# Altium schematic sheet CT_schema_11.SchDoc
size 386 x 385 mm
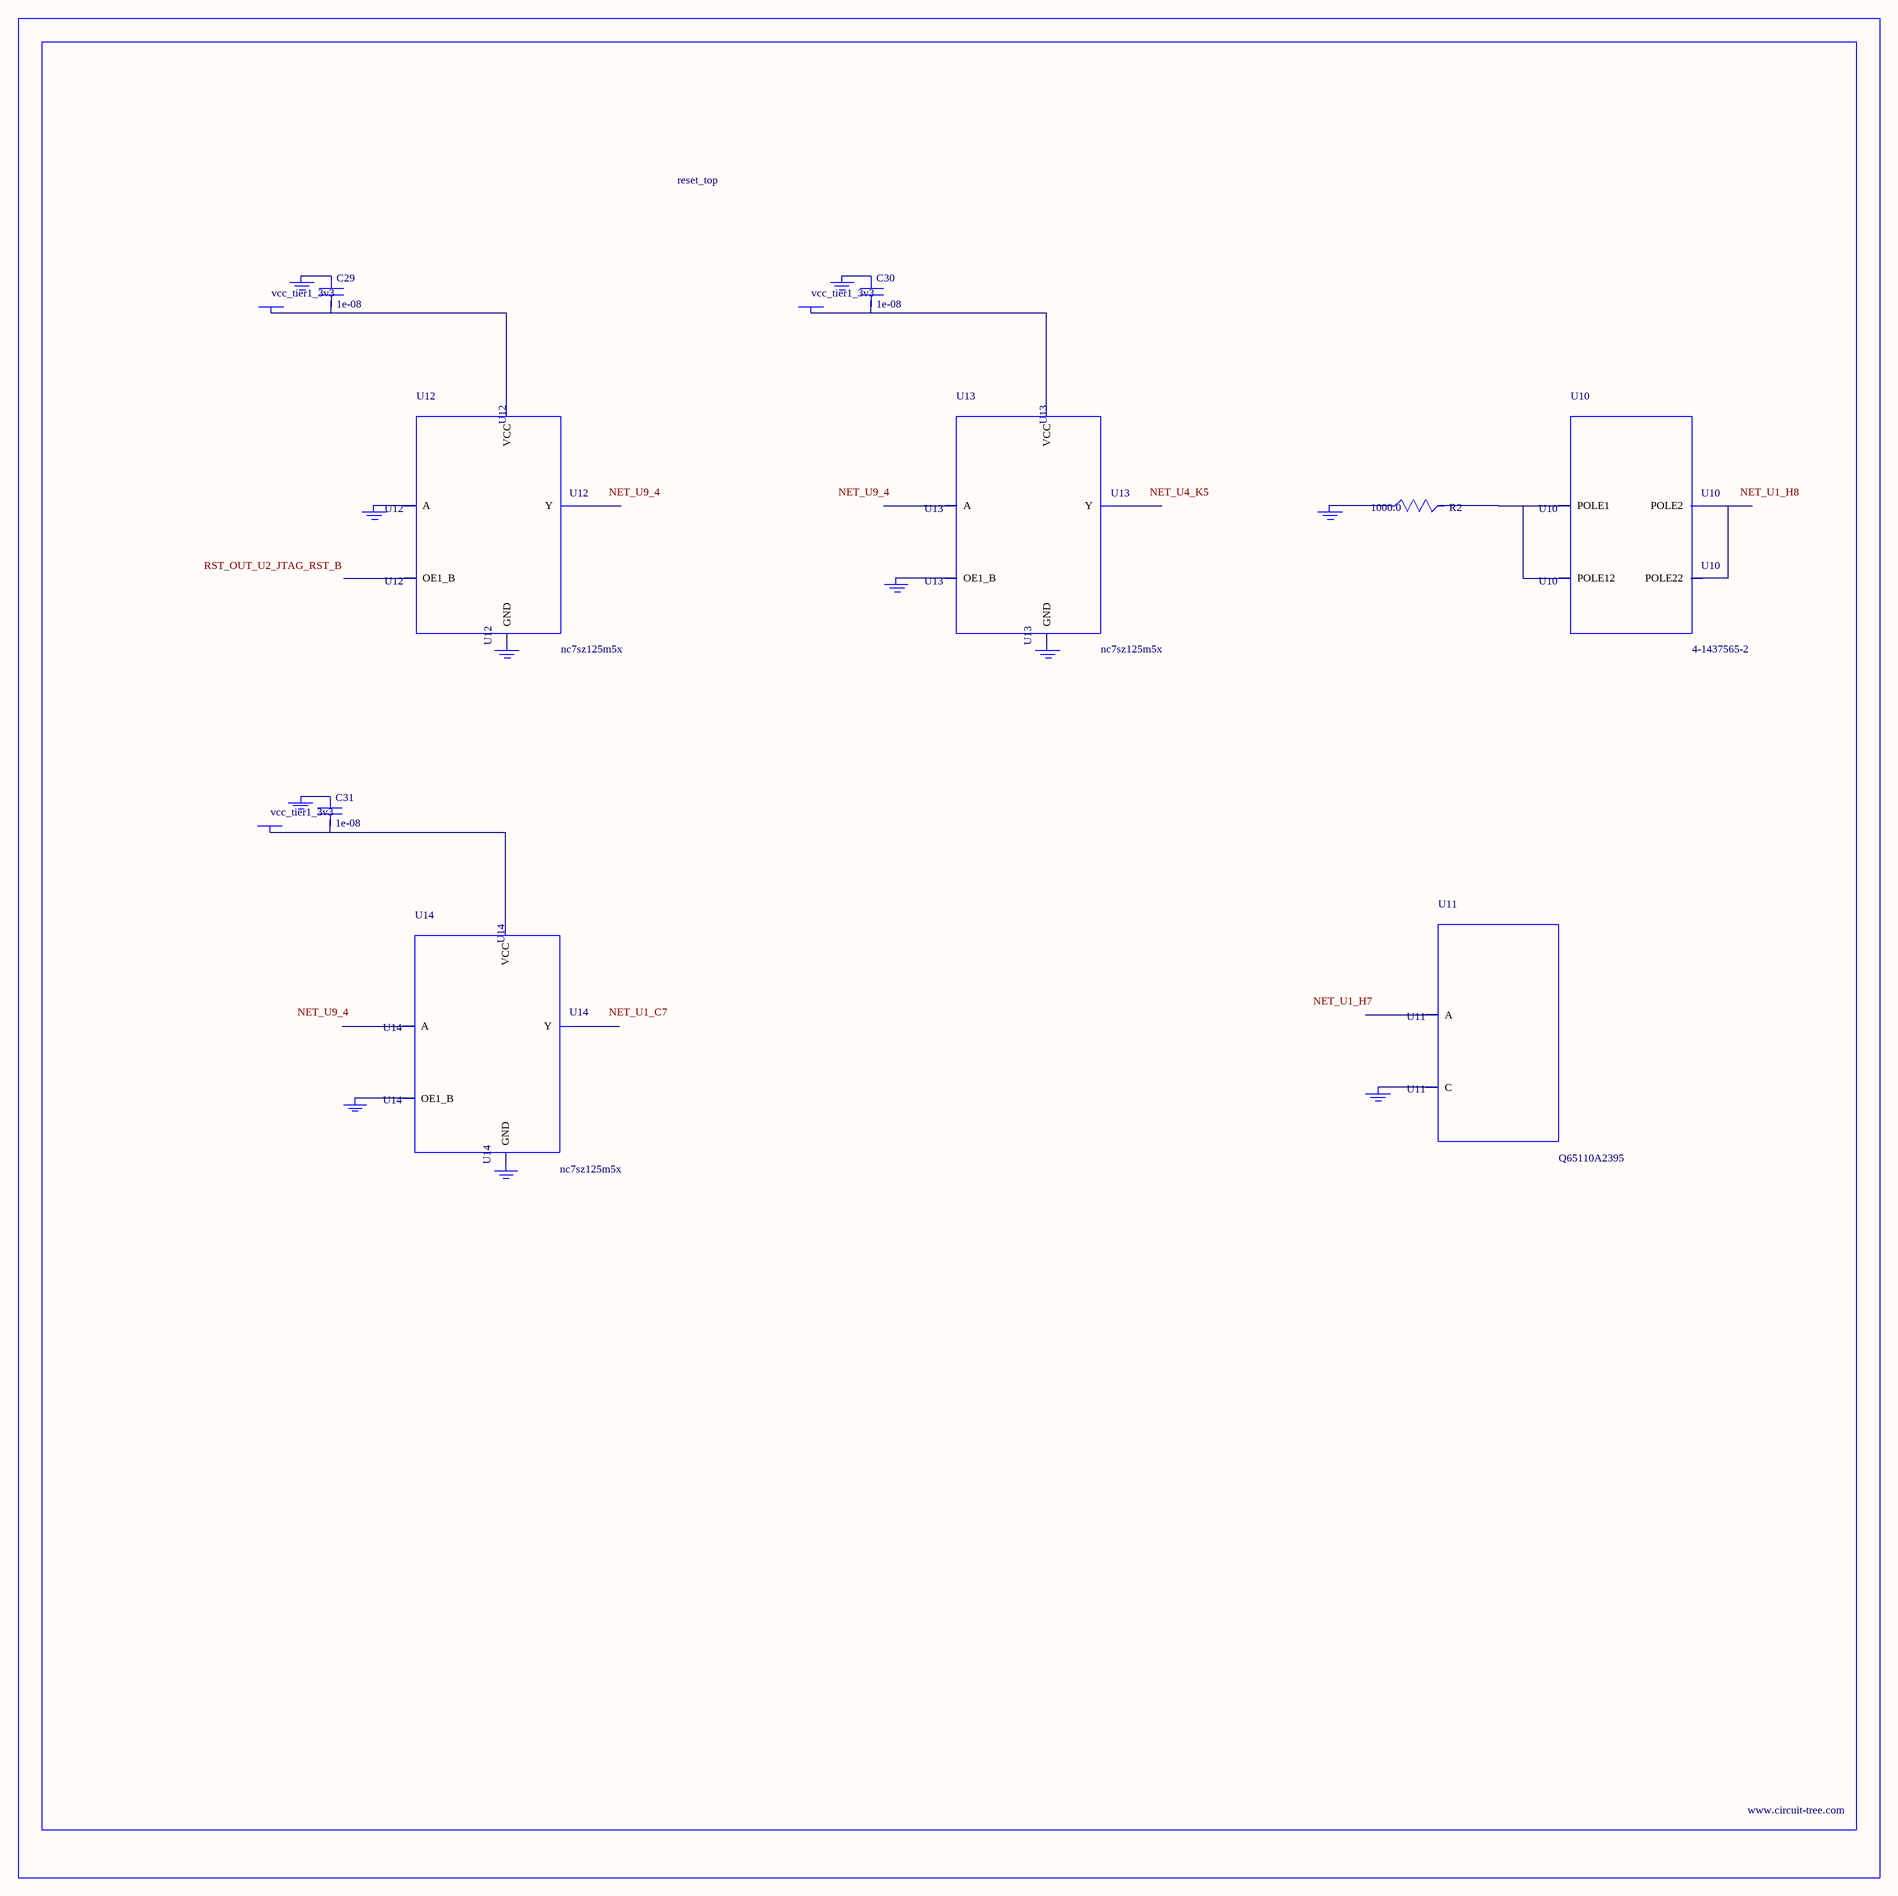
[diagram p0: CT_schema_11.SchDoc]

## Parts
BORDER10  (no value)
C29  1e-08  [C0402]
C30  1e-08  [C0402]
C31  1e-08  [C0402]
GND_INSTANCE_10_0  (no value)
GND_INSTANCE_10_1  (no value)
GND_INSTANCE_10_2  (no value)
GND_INSTANCE_10_3  (no value)
GND_INSTANCE_10_4  (no value)
GND_INSTANCE_10_5  (no value)
GND_INSTANCE_10_6  (no value)
GND_INSTANCE_10_7  (no value)
GND_INSTANCE_10_8  (no value)
GND_INSTANCE_10_9  (no value)
GND_INSTANCE_10_10  (no value)
POWER_INSTANCE_10_0  vcc_tier1_3v3
POWER_INSTANCE_10_1  vcc_tier1_3v3
POWER_INSTANCE_10_2  vcc_tier1_3v3
R2  1000.0  [R0603]
U10  4-1437565-2  [SW_4-1437565-2]
U11  Q65110A2395  [LGM67K-G1J2-24-Z]
U12  nc7sz125m5x  [NC7SZ125M5X]
U13  nc7sz125m5x  [NC7SZ125M5X]
U14  nc7sz125m5x  [NC7SZ125M5X]

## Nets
NetC29_1: C29.1 GND_INSTANCE_10_2.0(GND)
NetC29_2: C29.2 POWER_INSTANCE_10_0.0(PWR) U12.5(VCC)
NetC30_1: C30.1 GND_INSTANCE_10_5.0(GND)
NetC30_2: C30.2 POWER_INSTANCE_10_1.0(PWR) U13.5(VCC)
NetC31_1: C31.1 GND_INSTANCE_10_8.0(GND)
NetC31_2: C31.2 POWER_INSTANCE_10_2.0(PWR) U14.5(VCC)
NetGND_INSTANCE_10_0_0: GND_INSTANCE_10_0.0(GND) R2.1
NetGND_INSTANCE_10_1_0: GND_INSTANCE_10_1.0(GND) U11.C
NetGND_INSTANCE_10_3_0: GND_INSTANCE_10_3.0(GND) U12.2(A)
NetGND_INSTANCE_10_4_0: GND_INSTANCE_10_4.0(GND) U12.3(GND)
NetGND_INSTANCE_10_6_0: GND_INSTANCE_10_6.0(GND) U13.1(OE1_B)
NetGND_INSTANCE_10_7_0: GND_INSTANCE_10_7.0(GND) U13.3(GND)
NetGND_INSTANCE_10_9_0: GND_INSTANCE_10_9.0(GND) U14.1(OE1_B)
NetGND_INSTANCE_10_10_0: GND_INSTANCE_10_10.0(GND) U14.3(GND)
NetR2_2: R2.2 U10.1(POLE1) U10.2(POLE12)
NetU10_3: U10.3(POLE2) U10.4(POLE22)

Not connected (* = marked no-connect by the designer): U11 A; U12 1(OE1_B) 4(Y); U13 2(A) 4(Y); U14 2(A) 4(Y)

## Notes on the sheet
- Labels drawn without touching a wire or pin: NET_U1_C7, NET_U1_H7, NET_U1_H8, NET_U4_K5, NET_U9_4, RST_OUT_U2_JTAG_RST_B

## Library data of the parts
BORDER10 = BORDER_PAGE10
C29-C31 = C0402C103K3RAC
GND_INSTANCE_10_0-GND_INSTANCE_10_10 = GND
POWER_INSTANCE_10_0-POWER_INSTANCE_10_2 = PWR
R2 = RC0603JR-071KL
